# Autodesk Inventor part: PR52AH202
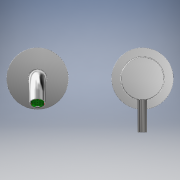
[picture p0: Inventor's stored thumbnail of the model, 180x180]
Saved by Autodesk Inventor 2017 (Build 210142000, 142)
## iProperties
Created: 2021-04
Part Number: PR52AH202
Material: Generico
Document SubType Name: Modeling
Designer: PIZZERA
Density: 1 g/cm^3
Appearance: Default
Author: PIZZERA
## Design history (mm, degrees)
feature "Base3"
node "Solido1"
node "Solido4"
